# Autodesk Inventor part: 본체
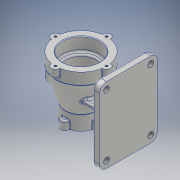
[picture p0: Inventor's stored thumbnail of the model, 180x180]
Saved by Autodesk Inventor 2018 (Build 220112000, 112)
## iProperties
Created: 2020-12
Part Number: 본체
Material: 알루미늄 6061
Document SubType Name: Modeling
Designer: home
Density: 2.7 g/cm^3
Appearance: 알루미늄 - 평지
Mass: 1030.13 g
Surface Area: 850.653 cm^2
Volume: 381.528 cm^3
Author: home
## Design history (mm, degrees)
sketch "스케치1"
  geometry: L1 (0, 50)-(0, -50); L2 (32, 50)-(32, 30); L3 (29, 27)-(29, 27); L4 (26, 24)-(26, -17); L5 (23, -20)-(23, -20); L6 (20, -23)-(20, -50); L7 (32, 50)-(44, 50); L8 (44, 50)-(44, 30); L9 (20, -50)-(27.5, -50); L10 (27.5, -50)-(27.5, -25); L11 (27.5, -25)-(44, 30); A1 r 3 centre (29, 30) between (29, 27) and (32, 30); A2 r 3 centre (29, 24) between (29, 27) and (26, 24); A3 r 3 centre (23, -17) between (23, -20) and (26, -17); A4 r 3 centre (23, -23) between (23, -20) and (20, -23); 6 further points
  constraints: 22 end point, 8 point on circle, 8 point on line, 8 tangent, 4 centre point, 4 perpendicular, 3 horizontal, 3 vertical, 2 equal radius, 1 coincident, 1 midpoint
  dimensions: "d0" = 100 distance of L1.start L1.end; "d1" = 23 distance of L2.start point (32, 27); "d2" = 64 diameter of L2 L1; "d3" = 47 distance of point (26, 27) point (26, -20); "d4" = 30 distance of point (20, -20) L6.end; "d5" = 52 diameter of L4 L1; "d6" = 40 diameter of L6 L1; "d8" = 55 diameter of L9.end L1; "d9" = 88 diameter of L8 L1; "d10" = 25 distance of L9.end L10.end; "d11" = 20 distance of L7.end L8.end; "d12" = 50 distance from line of L7 point (0, 0); "d13" = 3 radius of A1; "d14" = 3 radius of A3 (derived)
revolve "회전1" sketch "스케치1" stored, may be unused: angle "d15" = 90 deg
node "작업 평면1"
sketch "스케치2"
  geometry: L1 (-38, 65)-(38, 65); L2 (50, 53)-(50, -53); L3 (38, -65)-(-38, -65); L4 (-50, -53)-(-50, 53); A1 r 12 centre (-38, 53) between (-38, 65) and (-50, 53); A2 r 12 centre (38, 53) between (50, 53) and (38, 65); A3 r 12 centre (38, -53) between (38, -65) and (50, -53); A4 r 12 centre (-38, -53) between (-50, -53) and (-38, -65); 6 further points
  constraints: 8 end point, 8 point on circle, 8 tangent, 6 point on line, 4 centre point, 3 equal radius, 2 midpoint, 2 parallel, 1 horizontal, 1 horizontal alignment, 1 perpendicular, 1 vertical alignment
  dimensions: "d17" = 100 distance of point (50, -65) point (-50, -65); "d18" = 130 distance of point (50, 65) point (50, -65); "d19" = 12 radius of A1 (derived)
extrude "돌출1" join sketch "스케치2" distance "d20" = 12; taper "d21" = 0 deg
sketch "스케치3"
  geometry: L1 (-25.725, -24)-(-73.725, -24); L2 (-38.725, 24)-(-73.725, 24); L3 (-73.725, 24)-(-73.725, -24); L4 (-25.725, -24)-(-38.725, 24); 1 further point
  constraints: 8 end point, 2 horizontal alignment, 1 vertical, 1 vertical alignment
  dimensions: "d24" = 24 distance from line of L2 point (0, 0); "d25" = 48 distance between parallel lines of L1 L2; "d26" = 48 distance of L1.start L1.end; "d27" = 35 distance of L2.start L2.end; "d29" = 73.72534 distance from line of L3 point (0, 0)
extrude "돌출2" join sketch "스케치3" stored distance "d30" = 8; taper "d31" = 0 deg
sketch "스케치5"
  geometry: L1 (21, 25)-(76, 25); L2 (76, 25)-(76, -25); L3 (76, -25)-(21, -25); C1 r 32 at (0, 0) reference; 1 further point
  constraints: 6 end point, 2 perpendicular, 1 horizontal, 1 vertical alignment
  dimensions: "d35" = 25 distance from line of L1 point (0, 0); "d36" = 50 distance between parallel lines of L3 L1; "d38" = 55 distance of L1.start L1.end; "d40" = 76 distance from line of L2 point (0, 0)
feature "리브1" sketch "스케치5" dims "d41" = 1, "d42" = 8, "d43" = 0, "d44" = 0, "d45" = 1, "d46" = 1
node "작업 평면2"
sketch "스케치6"
  geometry: C1 r 17 at (0, 0); 1 further point
  constraints: 1 centre point, 1 coincident
  dimensions: "d48" = 34 diameter of C1
extrude "돌출3" join sketch "스케치6" stored distance "d49" = 8; taper "d50" = 0 deg
sketch "스케치7"
  geometry: C1 r 17 at (0, 0) reference; 1 further point
  constraints: 1 coincident
hole "구멍1" sketch "스케치7" at (0, 0) diameter "d51" = 22; stored, may be unused: countersink angle "d55" = 90 deg, drill point angle "d57" = 118 deg; dims "d52" = 6, "d53" = 28, "d54" = 1, "d56" = 45
chamfer "모따기1" distance "d58" = 1; stored, may be unused: second distance "d59" = 2, angle "d60" = 45 deg
sketch "스케치8"
  geometry: C1 r 7 at (-44, 0); 1 further point
  constraints: 1 centre point, 1 horizontal alignment
  dimensions: "d61" = 14 diameter of C1; "d62" = 44 distance of C1.centre point (0, 0)
extrude "돌출4" join sketch "스케치8" distance "d63" = 15; taper "d64" = 0 deg
sketch "스케치9"
  geometry: 2 further points
  constraints: 1 horizontal alignment
  dimensions: "d65" = 44 distance of point (0, 0) point (44, 0)
hole "구멍2" sketch "스케치9" at (0, 0) diameter "d66" = 4.134; stored, may be unused: countersink angle "d70" = 90 deg, drill point angle "d72" = 118 deg; dims "d67" = 9, "d68" = 28, "d69" = 1, "d71" = 11
fillet "모깎기2" dims "d74" = 3
fillet "모깎기4" dims "d76" = 1
sketch "스케치11"
  geometry: C1 r 7 at (27.5, 0); 1 further point
  constraints: 1 centre point, 1 horizontal alignment
  dimensions: "d80" = 14 diameter of C1; "d81" = 27.5 distance of C1.centre point (0, 0)
extrude "돌출5" join sketch "스케치11" distance "d82" = 15; taper "d83" = 0 deg
fillet "모깎기5" dims "d84" = 3
fillet "모깎기6" dims "d85" = 1
sketch "스케치12"
  geometry: A1 r 7 centre (0, 0) between (-0.127, -6.999) and (-0.127, 6.999) reference; 1 further point
hole "구멍3" sketch "스케치12" at (0, 0) diameter "d86" = 4.134; stored, may be unused: countersink angle "d90" = 90 deg, drill point angle "d92" = 118 deg; dims "d87" = 9, "d88" = 28, "d89" = 1, "d91" = 11
fillet "모깎기7" dims "d96" = 1
chamfer "모따기2" distance "d97" = 1; stored, may be unused: second distance "d98" = 2, angle "d99" = 45 deg
fillet "모깎기8" dims "d100" = 3
sketch "스케치13"
  geometry: A1 r 12 centre (53, -38) between (53, -50) and (65, -38) reference; A2 r 12 centre (53, 38) between (65, 38) and (53, 50) reference; A3 r 12 centre (-53, 38) between (-53, 50) and (-65, 38) reference; A4 r 12 centre (-53, -38) between (-65, -38) and (-53, -50) reference; 1 further point
hole "구멍4" sketch "스케치13" at (53, -38), (53, 38), (-53, 38), (-53, -38) diameter "d101" = 10; stored, may be unused: countersink angle "d105" = 90 deg, drill point angle "d107" = 118 deg; dims "d102" = 9, "d103" = 28, "d104" = 1, "d106" = 10
fillet "모깎기9" dims "d108" = 3
fillet "모깎기10" dims "d109" = 3
fillet "모깎기11" dims "d110" = 3
fillet "모깎기12" dims "d111" = 3
sketch "스케치14"
  geometry: L1 (53, 50)-(-53, 50) reference; 2 further points
  constraints: 1 vertical alignment, 1 other
  dimensions: "d113" = 10 distance from line of L1 point (0, 40)
feature "엠보싱1" sketch "스케치14" dims "d0" = 100, "d1" = 23, "d2" = 64, "d3" = 47, "d4" = 30, "d5" = 52, "d6" = 40, "d8" = 55, "d9" = 88, "d10" = 25, "d11" = 20, "d12" = 50, "d13" = 3, "d14" = 3 (derived), "d114" = 0.5, "d115" = 0
fillet "모깎기13" dims "d116" = 3
node "솔리드1"
pattern_circular "원형 패턴1" dims "d78" = 360 deg
pattern_circular "원형 패턴2" dims "d94" = 360 deg
other parameters: "d16" = 82, "d47" = -45
